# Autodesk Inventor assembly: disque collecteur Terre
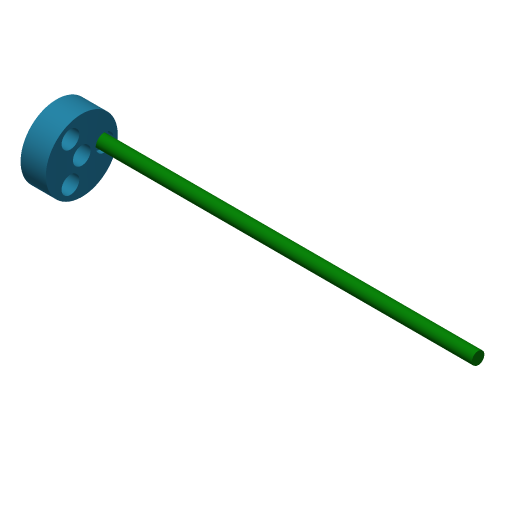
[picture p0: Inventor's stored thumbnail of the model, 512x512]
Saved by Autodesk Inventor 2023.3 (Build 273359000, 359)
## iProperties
Created: 2017-03
Part Number: disque collecteur Terre
Document SubType Name: Assembly
Designer: thierry.jost
Author: thierry.jost
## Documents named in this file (3)
- C:\Travail\BTS TechCom\2-TechnoIndus\21-Meca\214-Systémes Industriels-SI\2141-Pièces Ecrites\21411-Cycle1\214112-TP02Eolienne\2141122-DossierTechniqueEolienne\21411223-Maquette numerique\CEC-Eolienne\Disque collecteur\20t-Disque collecteur Terre.iam
- C:\Travail\BTS TechCom\2-TechnoIndus\21-Meca\214-Systémes Industriels-SI\2141-Pièces Ecrites\21411-Cycle1\214112-TP02Eolienne\2141122-DossierTechniqueEolienne\21411223-Maquette numerique\CEC-Eolienne\Disque collecteur\Disque collecteur n.ipt
- C:\Travail\BTS TechCom\2-TechnoIndus\21-Meca\214-Systémes Industriels-SI\2141-Pièces Ecrites\21411-Cycle1\214112-TP02Eolienne\2141122-DossierTechniqueEolienne\21411223-Maquette numerique\CEC-Eolienne\Disque collecteur\terre.ipt
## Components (2 placed, 2 different names)
1. Disque collecteur n:1 — Insert:1
2. terre:1 — Insert:1
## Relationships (1: Insert 1)
- Insert:1: Disque collecteur n:1 ↔ terre:1
